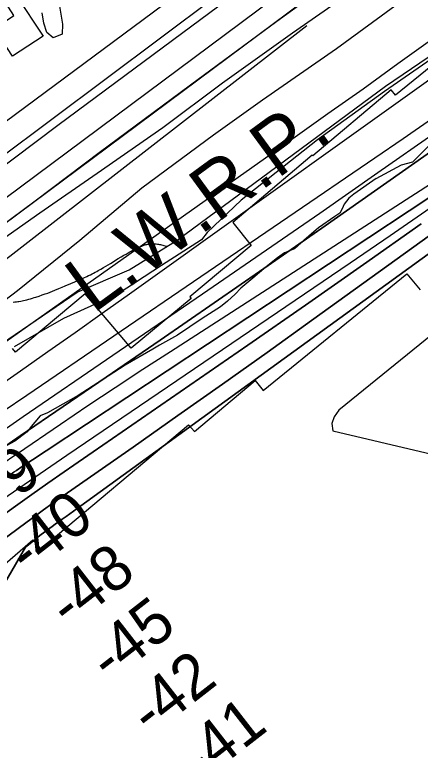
# Model space of a CAD drawing. Extents: x 3477039 to 3515015, y 546746 to 572297.
# Drawn here: x 3482639 to 3483241, y 558686 to 559777 of the extents above; entities that cross this region are included whole.
import ezdxf

# ---------------------------------------------------------------- set-up
doc = ezdxf.new("R2010")
doc.units = 0
for name, color, linetype in [('V-BLDG-OTLN', 7, 'Continuous'), ('V-FLOD-BASE', 7, 'Continuous'), ('V-LEVE-TOET', 7, 'Continuous'), ('V-RIVR-EDGE', 7, 'Continuous'), ('V-RIVR-RANG', 7, 'Continuous'), ('V-ROAD-CNTR', 7, 'Continuous'), ('V-RRAP-FSHR', 7, 'Continuous'), ('V-RRAP-RVMT', 7, 'Continuous'), ('V-SITE-VEGE', 7, 'Continuous'), ('V-SURV-LINE', 7, 'Continuous'), ('V-TOPO-DPTH', 7, 'Continuous'), ('V-TOPO-MAJR', 7, 'Continuous'), ('V-TOPO-MINR', 7, 'Continuous'), ('V-TOPO-SHOR', 7, 'Continuous'), ('V-TOPO-WATR', 7, 'Continuous'), ('V-TOPO-WATR-IDEN', 7, 'Continuous')]:
    doc.layers.add(name, color=color, linetype=linetype)

msp = doc.modelspace()

# ---------------------------------------------------------------- linework, layer by layer
at = {"layer": 'V-BLDG-OTLN'}
msp.add_lwpolyline([(3482638.1, 559776.2), (3482625.3, 559795.7), (3482641.4, 559806.3), (3482681.3, 559745.6), (3482636, 559715.7), (3482608.9, 559757)], close=True, dxfattribs=at)
at = {"layer": 'V-FLOD-BASE'}
msp.add_lwpolyline([(3482382.9, 559248.9), (3482364.8, 559272), (3482401.5, 559301.2), (3482530.3, 559398.1), (3482669.5, 559501.2), (3482766.4, 559574.2), (3482900, 559673.3), (3483028.3, 559767.9), (3483135.8, 559846), (3483258.8, 559933.5), (3483358, 560002.3), (3483466.8, 560085.2), (3483528.9, 560136.6), (3483563.8, 560167.6), (3483599.3, 560196.2), (3483672.6, 560249.2), (3483768.9, 560321.6), (3483869.4, 560401), (3483974.7, 560480.9), (3484043.8, 560532.9), (3484090.5, 560567.9), (3484094.7, 560564.3)], dxfattribs=at)
at = {"layer": 'V-LEVE-TOET'}
for points in [[(3484546.9, 561015), (3484410.9, 560904), (3484276.1, 560799), (3484222.1, 560759.6), (3484143.1, 560701), (3484017.8, 560608.8), (3483855.8, 560483.3), (3483732.8, 560381.7), (3483580.9, 560267.9), (3483437.9, 560159.3), (3483302.5, 560057.2), (3483187.3, 559976.8), (3483022.3, 559850.1), (3482873.4, 559739.2), (3482703.1, 559613.2), (3482541.8, 559491.8), (3482433.6, 559410.7), (3482383.4, 559374.9), (3482356.2, 559355.3), (3482282.9, 559299.3), (3482194.2, 559234), (3482159.4, 559205)], [(3482025.5, 558992.6), (3482136.7, 559079), (3482229.5, 559149.6), (3482279.1, 559182.3), (3482296.8, 559188), (3482307.4, 559191.5), (3482316.9, 559196.2), (3482326.3, 559200.2), (3482331.6, 559204.3), (3482346.4, 559211.3), (3482366.8, 559228.5), (3482383.6, 559242.8), (3482391.4, 559253.9), (3482399.1, 559268.6), (3482411, 559284.4), (3482420.5, 559295.5), (3482509.1, 559360.9), (3482573.6, 559411.1), (3482676.4, 559483.4), (3482761.5, 559542.3), (3482859, 559609.9), (3482947.6, 559676.5), (3483051.7, 559750.5), (3483162.2, 559827.5)]]:
    msp.add_lwpolyline(points, dxfattribs=at)
at = {"layer": 'V-RIVR-EDGE'}
for p, q in [((3483175.7, 559534.4), (3483142.5, 559510.9)), ((3483135.1, 559505), (3483128.4, 559496.2)), ((3483142.5, 559510.9), (3483135.1, 559505)), ((3483128.4, 559496.2), (3483125.5, 559489.5)), ((3483121.8, 559482.9), (3483114.4, 559477.8)), ((3483125.5, 559489.5), (3483121.8, 559482.9)), ((3483114.4, 559477.8), (3483090, 559460.9)), ((3483090, 559460.9), (3483079.6, 559452.4)), ((3483079.6, 559452.4), (3483064.5, 559439)), ((3483064.5, 559439), (3483054.4, 559430.1)), ((3483054.4, 559430.1), (3483039.9, 559424)), ((3483029.3, 559416.7), (3483012.5, 559403.4)), ((3483039.9, 559424), (3483029.3, 559416.7)), ((3483012.5, 559403.4), (3482992.9, 559386.1)), ((3482992.9, 559386.1), (3482975, 559371.6)), ((3482966.5, 559362.7), (3482955.3, 559352.1)), ((3482975, 559371.6), (3482966.5, 559362.7)), ((3482955.3, 559352.1), (3482944.7, 559343.8)), ((3482944.7, 559343.8), (3482917.3, 559326.5)), ((3482917.3, 559326.5), (3482880.9, 559301.5)), ((3482880.9, 559301.5), (3482854.1, 559287)), ((3482854.1, 559287), (3482844, 559280.9)), ((3482844, 559280.9), (3482803.1, 559257)), ((3482803.1, 559257), (3482769.6, 559235.2)), ((3482769.6, 559235.2), (3482733.2, 559212.4)), ((3482733.2, 559212.4), (3482687.9, 559186.3)), ((3482687.9, 559186.3), (3482677.2, 559181.8)), ((3482677.2, 559181.8), (3482668.8, 559172.4)), ((3482663.8, 559166.2), (3482657.6, 559158.4)), ((3482668.8, 559172.4), (3482663.8, 559166.2)), ((3482657.6, 559158.4), (3482639.2, 559144.5)), ((3482639.2, 559144.5), (3482627.4, 559137.8))]:
    msp.add_line(p, q, dxfattribs=at)
msp.add_lwpolyline([(3483175.7, 559534.4), (3483213.5, 559554.5), (3483230.3, 559559.2), (3483288.1, 559616.7), (3483328.9, 559635.8), (3483360.2, 559647.8)], dxfattribs=at)
at = {"layer": 'V-ROAD-CNTR'}
for points in [[(3483006, 559900.9), (3482419.4, 559465.9), (3482031.3, 559180.6), (3481456.7, 558757.4), (3481230.5, 558590.7)], [(3483006, 559900.9), (3482419.4, 559465.9), (3482399.6, 559451.4)], [(3482665.4, 559356.7), (3482668, 559357.5), (3482670.5, 559358.3), (3482675.4, 559359.8), (3482679.9, 559361.4), (3482684.2, 559362.9), (3482688.1, 559364.3), (3482691.8, 559365.7), (3482695.2, 559367.1), (3482698.5, 559368.3), (3482704.5, 559370.8), (3482709.8, 559373), (3482714.3, 559374.9), (3482722.3, 559378.4), (3482728.3, 559381.1), (3482746.2, 559389), (3482748.9, 559390.3), (3482751.5, 559391.5), (3482754, 559392.7), (3482756.3, 559393.9), (3482758.6, 559395.1), (3482760.9, 559396.3), (3482763, 559397.5), (3482767.1, 559399.8), (3482771, 559402), (3482774.5, 559404.2), (3482781.2, 559408.2), (3482792.9, 559415.3), (3482797.3, 559418), (3482801.1, 559420.3), (3482804.5, 559422.2), (3482807.5, 559423.9), (3482810.1, 559425.4), (3482812.3, 559426.6), (3482814.4, 559427.7), (3482817.9, 559429.5), (3482820.6, 559430.8), (3482822.6, 559431.7), (3482825.6, 559433.1), (3482828.7, 559434.5), (3482829.7, 559434.9), (3482830.7, 559435.2), (3482831.7, 559435.6), (3482832.7, 559435.9), (3482833.7, 559436.1), (3482834.6, 559436.3), (3482835.5, 559436.5), (3482836.4, 559436.7), (3482838.2, 559436.9), (3482839.8, 559437.1), (3482841.4, 559437.2), (3482842.8, 559437.3), (3482844.2, 559437.3), (3482845.5, 559437.3), (3482846.8, 559437.2), (3482847.9, 559437.2), (3482849, 559437.1), (3482851, 559436.8), (3482852.8, 559436.6), (3482854.3, 559436.3), (3482855.7, 559436.1), (3482856.9, 559435.8), (3482858.9, 559435.3), (3482860.4, 559434.9), (3482862.6, 559434.3), (3482864.8, 559433.6)], [(3482636.9, 559350.9), (3482639.5, 559351.2), (3482641.7, 559351.4), (3482643.6, 559351.7), (3482645.3, 559351.9), (3482648.2, 559352.4), (3482650.4, 559352.8), (3482652.1, 559353.1), (3482654.5, 559353.7), (3482657, 559354.3), (3482659.9, 559355.1), (3482662.7, 559355.9), (3482665.4, 559356.7)]]:
    msp.add_lwpolyline(points, dxfattribs=at)
at = {"layer": 'V-RRAP-FSHR'}
msp.add_lwpolyline([(3481235.5, 558175), (3481260.4, 558193.2), (3481664.8, 558468.2), (3481750.1, 558561.3), (3481840.8, 558681.4), (3481906.4, 558774.6), (3482006.9, 558887.3), (3482130.2, 558983.5), (3482201, 559023.4), (3482476.9, 559192.1), (3482732, 559365.8), (3482809.3, 559398.5), (3482880.6, 559442.7), (3483189.7, 559671.5), (3483435.4, 559838.7), (3483794.7, 560115.6), (3484011.1, 560303.9), (3484237, 560525.2), (3484364.2, 560616.5), (3484735.6, 560876.4)], dxfattribs=at)
at = {"layer": 'V-RRAP-RVMT'}
for p, q in [((3483318.6, 559751), (3483204.3, 559658)), ((3483197.9, 559665.8), (3483081.7, 559567.9)), ((3483204.3, 559658), (3483197.9, 559665.8)), ((3483080.8, 559569), (3482963, 559468.8)), ((3483081.7, 559567.9), (3483080.8, 559569)), ((3482963, 559468.8), (3482990.3, 559434.7)), ((3482990.3, 559434.7), (3482899.4, 559358.6)), ((3483008.2, 559219.5), (3483221.3, 559392.6)), ((3483221.3, 559392.6), (3483241.4, 559369.1)), ((3482743.9, 559362.9), (3482640.5, 559276.7)), ((3482812.1, 559282.4), (3482743.9, 559362.9)), ((3482901.4, 559356.2), (3482812.1, 559282.4)), ((3482899.4, 559358.6), (3482901.4, 559356.2)), ((3482640.5, 559276.7), (3482635.9, 559281.9)), ((3482905.9, 559158.6), (3482996.3, 559234.3)), ((3482996.3, 559234.3), (3483008.2, 559219.5)), ((3482678, 558984.6), (3482897.4, 559168.7)), ((3482897.4, 559168.7), (3482905.9, 559158.6)), ((3482442.1, 558806.3), (3482666.2, 558997.8)), ((3482666.2, 558997.8), (3482678, 558984.6))]:
    msp.add_line(p, q, dxfattribs=at)
at = {"layer": 'V-SITE-VEGE'}
for points in [[(3482530, 559281.7), (3482643.5, 559368.1), (3482735.8, 559442.8), (3482828, 559520.5), (3482934.4, 559599.2), (3483007.1, 559651.2), (3483117, 559727.5), (3483224, 559805.7)], [(3482705.4, 559793.2), (3482709.9, 559763.2), (3482709.8, 559748.4), (3482696.2, 559743.2), (3482686.9, 559750.9), (3482682.2, 559765.1), (3482680, 559780.4)], [(3483275.3, 559723.6), (3483188.4, 559663.6), (3483088.5, 559591.8), (3482975.6, 559501.9), (3482924.7, 559454), (3482916.4, 559443.4), (3482857.3, 559405), (3482792.9, 559363), (3482711.5, 559326.5), (3482638.3, 559284.5)]]:
    msp.add_lwpolyline(points, dxfattribs=at)
at = {"layer": 'V-SURV-LINE'}
for points in [[(3482248, 559224.3), (3483493.3, 560151.6)], [(3483511.2, 560127.5), (3482265.9, 559200.2)]]:
    msp.add_lwpolyline(points, dxfattribs=at)
at = {"layer": 'V-TOPO-DPTH'}
for points in [[(3483403.1, 559676.9), (3483095.1, 559460.8), (3483015.3, 559405.1), (3482935.4, 559349.6), (3482855.3, 559294.4), (3482775.1, 559239.4), (3482647.5, 559152.2), (3482631, 559140.9), (3482614.6, 559129.5), (3482598.2, 559118), (3482581.9, 559106.4), (3481898.8, 558618.1)], [(3481898.8, 558618.1), (3482581.9, 559106.4), (3482598.2, 559118), (3482614.6, 559129.5), (3482631, 559140.9), (3482647.5, 559152.2), (3482775.1, 559239.4), (3482855.3, 559294.4), (3482935.4, 559349.6), (3483015.3, 559405.1), (3483095.1, 559460.8), (3483403.1, 559676.9)], [(3483258.1, 559622.4), (3483216.1, 559593.4), (3483174.1, 559564.5), (3482657, 559212), (3482622.2, 559188.2), (3482587.5, 559164.4), (3482552.8, 559140.5), (3482518.2, 559116.5), (3482489.9, 559096.8), (3482441.2, 559062.9), (3482392.6, 559028.9), (3482344, 558994.9), (3482295.5, 558960.7), (3481776.8, 558595.1), (3481757.2, 558581.2), (3481737.6, 558567.3), (3481718.1, 558553.4), (3481698.6, 558539.5), (3481539, 558425.1), (3481447.7, 558359.2), (3481356.7, 558292.7), (3481266.1, 558225.6), (3481235.3, 558202.6)], [(3483466.9, 559602.1), (3483079.9, 559323.5), (3483013.9, 559276.2), (3482947.8, 559229.1), (3482881.4, 559182.3), (3482814.9, 559135.7), (3482706.4, 559059.9), (3482694.1, 559051.2), (3482681.9, 559042.5), (3482669.8, 559033.7), (3482657.7, 559024.8), (3482479.5, 558892.9), (3482378.9, 558817.4), (3482279, 558741), (3482180.1, 558663.2), (3482081.9, 558584.6), (3481895.7, 558433.4), (3481878.6, 558419.3), (3481861.7, 558405.2), (3481845, 558390.8), (3481828.4, 558376.2), (3481238.6, 557604.5)], [(3481238.6, 557604.5), (3481828.4, 558376.2), (3481845, 558390.8), (3481861.7, 558405.2), (3481878.6, 558419.3), (3481895.7, 558433.4), (3482081.9, 558584.6), (3482180.1, 558663.2), (3482279, 558741), (3482378.9, 558817.4), (3482479.5, 558892.9), (3482657.7, 559024.8), (3482669.8, 559033.7), (3482681.9, 559042.5), (3482694.1, 559051.2), (3482706.4, 559059.9), (3482814.9, 559135.7), (3482881.4, 559182.3), (3482947.8, 559229.1), (3483013.9, 559276.2), (3483079.9, 559323.5), (3483466.9, 559602.1)], [(3483463.3, 559574.2), (3482731.9, 559044.5), (3482726.4, 559040.5), (3482720.9, 559036.5), (3482715.4, 559032.6), (3482709.8, 559028.7), (3482700.7, 559022.2), (3482699.7, 559021.5), (3482696.8, 559019.4), (3482683.9, 559009.8), (3482676.6, 559004.2), (3482669.3, 558998.5), (3482662.2, 558992.7), (3482655.1, 558986.9), (3482156.2, 558124.3), (3482132.5, 558103.3), (3482108.4, 558082.6), (3482083.8, 558062.4), (3482059, 558042.6)], [(3482088.1, 558066), (3482108.4, 558082.6), (3482132.5, 558103.3), (3482156.2, 558124.3), (3482655.1, 558986.9), (3482662.2, 558992.7), (3482669.3, 558998.5), (3482676.6, 559004.2), (3482683.9, 559009.8), (3482696.8, 559019.4), (3482699.7, 559021.5), (3482700.7, 559022.2), (3482709.8, 559028.7), (3482715.4, 559032.6), (3482720.9, 559036.5), (3482726.4, 559040.5), (3482731.9, 559044.5), (3483463.3, 559574.2)], [(3483284.6, 559525.8), (3482685.8, 559129.9), (3482679, 559125.5), (3482672.3, 559121), (3482665.5, 559116.6), (3482658.8, 559112.2), (3482648.7, 559105.6), (3482647, 559104.4), (3482645.2, 559103.3), (3482641.8, 559101), (3482638.4, 559098.7), (3482638.1, 559098.4), (3482637.7, 559098.2), (3482630.2, 559092.8), (3482626.2, 559089.9), (3482622.1, 559087), (3482618, 559084), (3482614, 559081.1), (3481836.8, 558514.1)], [(3481836.8, 558514.1), (3482614, 559081.1), (3482618, 559084), (3482622.1, 559087), (3482626.2, 559089.9), (3482630.2, 559092.8), (3482637.7, 559098.2), (3482638.1, 559098.4), (3482638.4, 559098.7), (3482641.8, 559101), (3482645.2, 559103.3), (3482647, 559104.4), (3482648.7, 559105.6), (3482658.8, 559112.2), (3482665.5, 559116.6), (3482672.3, 559121), (3482679, 559125.5), (3482685.8, 559129.9), (3483284.6, 559525.8)], [(3482028.4, 558607), (3482069.7, 558636.9), (3482616.6, 559031), (3482640.5, 559048.1), (3482664.4, 559065.1), (3482688.4, 559081.9), (3482712.5, 559098.7), (3482985.1, 559286.8), (3483071.1, 559346.5), (3483157, 559406.5), (3483242.5, 559466.9)], [(3482028.4, 558607), (3482069.7, 558636.9), (3482616.6, 559031), (3482640.5, 559048.1), (3482664.4, 559065.1), (3482688.4, 559081.9), (3482712.5, 559098.7), (3482985.1, 559286.8), (3483071.1, 559346.5), (3483157, 559406.5), (3483242.5, 559466.9)]]:
    msp.add_lwpolyline(points, dxfattribs=at)
at = {"layer": 'V-TOPO-MAJR'}
for points in [[(3483072.9, 559760.8), (3482514.1, 559327.7), (3482497.4, 559315), (3482480.5, 559302.5), (3482463.4, 559290.4), (3482446.2, 559278.4), (3482033.9, 558998.6)], [(3483536.1, 559527.3), (3483120.6, 559190.6), (3483113.5, 559180.7), (3483109.9, 559170.5), (3483111.5, 559159.8), (3483388.8, 559094.3)]]:
    msp.add_lwpolyline(points, dxfattribs=at)
at = {"layer": 'V-TOPO-MINR'}
for points in [[(3483259.8, 559741.6), (3483208.1, 559704.3), (3483156.3, 559667.1), (3483104.3, 559630.1), (3483052.3, 559593.2), (3482564.6, 559248.9), (3482550.9, 559239.2), (3482537.1, 559229.5), (3482523.3, 559219.8), (3482509.5, 559210.1), (3482284.6, 559051.9), (3482184.9, 558982.2), (3482085, 558912.8), (3481984.8, 558843.9)], [(3483338.7, 559740.6), (3482809.6, 559362.6), (3482769.2, 559333.9), (3482728.8, 559305.3), (3482688.3, 559276.8), (3482647.7, 559248.3), (3482581.5, 559202.2), (3482574, 559196.9), (3482566.4, 559191.6), (3482558.9, 559186.3), (3482551.4, 559181), (3482378.5, 559058.1), (3482284.4, 558991.4), (3482190.4, 558924.8), (3482096.2, 558858.3), (3482002, 558791.9)], [(3483258.1, 559622.4), (3483216.1, 559593.4), (3483174.1, 559564.5), (3482657, 559212), (3482622.2, 559188.2), (3482587.5, 559164.4), (3482552.8, 559140.5), (3482518.2, 559116.5), (3482489.9, 559096.8), (3482441.2, 559062.9), (3482392.6, 559028.9), (3482344, 558994.9), (3482295.5, 558960.7), (3481776.8, 558595.1), (3481757.2, 558581.2), (3481737.6, 558567.3), (3481718.1, 558553.4), (3481698.6, 558539.5), (3481539, 558425.1), (3481447.7, 558359.2), (3481356.7, 558292.7), (3481266.1, 558225.6), (3481235.3, 558202.6)], [(3483264.8, 559603.2), (3483178.5, 559542.6), (3483092, 559482.3), (3483005.2, 559422.3), (3482918.2, 559362.6), (3482651.9, 559180.6), (3482626.8, 559163.3), (3482601.7, 559146), (3482576.8, 559128.5), (3482551.8, 559111), (3482210.2, 558869.5), (3482134.1, 558815.6), (3482058.1, 558761.7), (3481982.2, 558707.5), (3481906.4, 558653.3), (3481770.7, 558556.1), (3481762.8, 558550.4), (3481754.9, 558544.7), (3481747, 558539), (3481739.2, 558533.3), (3481235.5, 558167.5)], [(3483466.9, 559602.1), (3483079.9, 559323.5), (3483013.9, 559276.2), (3482947.8, 559229.1), (3482881.4, 559182.3), (3482814.9, 559135.7), (3482706.4, 559059.9), (3482694.1, 559051.2), (3482681.9, 559042.5), (3482669.8, 559033.7), (3482657.7, 559024.8), (3482479.5, 558892.9), (3482378.9, 558817.4), (3482279, 558741), (3482180.1, 558663.2), (3482081.9, 558584.6), (3481895.7, 558433.4), (3481878.6, 558419.3), (3481861.7, 558405.2), (3481845, 558390.8), (3481828.4, 558376.2), (3481238.6, 557604.5)], [(3483463.3, 559574.2), (3482731.9, 559044.5), (3482726.4, 559040.5), (3482720.9, 559036.5), (3482715.4, 559032.6), (3482709.8, 559028.7), (3482700.7, 559022.2), (3482699.7, 559021.5), (3482696.8, 559019.4), (3482683.9, 559009.8), (3482676.6, 559004.2), (3482669.3, 558998.5), (3482662.2, 558992.7), (3482655.1, 558986.9), (3482156.2, 558124.3), (3482132.5, 558103.3), (3482108.4, 558082.6), (3482083.8, 558062.4), (3482059, 558042.6)], [(3483284.6, 559525.8), (3482685.8, 559129.9), (3482679, 559125.5), (3482672.3, 559121), (3482665.5, 559116.6), (3482658.8, 559112.2), (3482648.7, 559105.6), (3482647, 559104.4), (3482645.2, 559103.3), (3482641.8, 559101), (3482638.4, 559098.7), (3482638.1, 559098.4), (3482637.7, 559098.2), (3482630.2, 559092.8), (3482626.2, 559089.9), (3482622.1, 559087), (3482618, 559084), (3482614, 559081.1), (3481836.8, 558514.1)], [(3483263.6, 559530.5), (3483227.1, 559507), (3482870.4, 559277.2), (3482829.4, 559250.6), (3482788.5, 559223.7), (3482747.8, 559196.6), (3482707.3, 559169.2), (3482643.3, 559125.7), (3482634.9, 559119.9), (3482626.5, 559114.1), (3482618.1, 559108.2), (3482609.8, 559102.3), (3482432.7, 558975.7), (3482336, 558906.3), (3482239.4, 558836.8), (3482142.9, 558766.9), (3482046.7, 558696.9)], [(3483256.2, 559490.3), (3483196.8, 559449.3), (3483137.2, 559408.6), (3482716.8, 559123.3), (3482684.9, 559101.5), (3482653.1, 559079.7), (3482621.5, 559057.6), (3482589.9, 559035.4), (3482495.4, 558968.7), (3482416.8, 558912.9), (3482338.4, 558856.7), (3482260.4, 558800), (3482182.6, 558743), (3481832.4, 558484.7), (3481822.3, 558477.3), (3481812.3, 558469.8), (3481802.2, 558462.2), (3481792.2, 558454.7), (3481236.3, 558034.2)], [(3483242.5, 559466.9), (3483157, 559406.5), (3483071.1, 559346.5), (3482985.1, 559286.8), (3482712.5, 559098.7), (3482688.4, 559081.9), (3482664.4, 559065.1), (3482640.5, 559048.1), (3482616.6, 559031), (3482069.7, 558636.9), (3482028.4, 558607)]]:
    msp.add_lwpolyline(points, dxfattribs=at)
at = {"layer": 'V-TOPO-SHOR'}
msp.add_line((3483133.3, 559950.5), (3482442.8, 559433.6), dxfattribs=at)
at = {"layer": 'V-TOPO-WATR'}
msp.add_lwpolyline([(3483403.1, 559676.9), (3483095.1, 559460.8), (3483015.3, 559405.1), (3482935.4, 559349.6), (3482855.3, 559294.4), (3482775.1, 559239.4), (3482647.5, 559152.2), (3482631, 559140.9), (3482614.6, 559129.5), (3482598.2, 559118), (3482581.9, 559106.4), (3481898.8, 558618.1)], dxfattribs=at)

# ---------------------------------------------------------------- texts
at = {"layer": 'V-RIVR-RANG'}
for s, p in [('-9', (3482620.8, 559041.4)), ('-40', (3482658.3, 558943.9)), ('-48', (3482719.8, 558865)), ('-45', (3482780.2, 558785.3)), ('-42', (3482840.6, 558705.6)), ('-41', (3482915, 558636.8))]:
    msp.add_text(s, height=67, rotation=37.9073, dxfattribs=at).set_placement(p)
at = {"layer": 'V-TOPO-WATR-IDEN'}
msp.add_text('L.W.R.P.', height=83, rotation=36.2042, dxfattribs=at).set_placement((3482755.3, 559332.6))

doc.saveas('drawing.dxf')
